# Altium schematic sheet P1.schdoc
size 297 x 209 mm; Symbol: Drawing-Symbol_A4; @Project Name: fmcw; @Page Count: 1; @Update Date: 2026-07-30; @Create Date: 2026-07-30; @Schematic Name: Schematic1; @Page No: 1; @Page Name: P1; Company: EasyEDA.com; Version: V1.0; Page Size: A4; Device: Drawing-Symbol_A4; @Create Time: 13:49:19; @Update Time: 13:49:19; Border: 1; Width: 1170; Height: 825; Region Start: 1; X Region Count: 6; Y Region Count: 4; Blade Width: 10; Title Block Position: 3; @Board Name: Board1
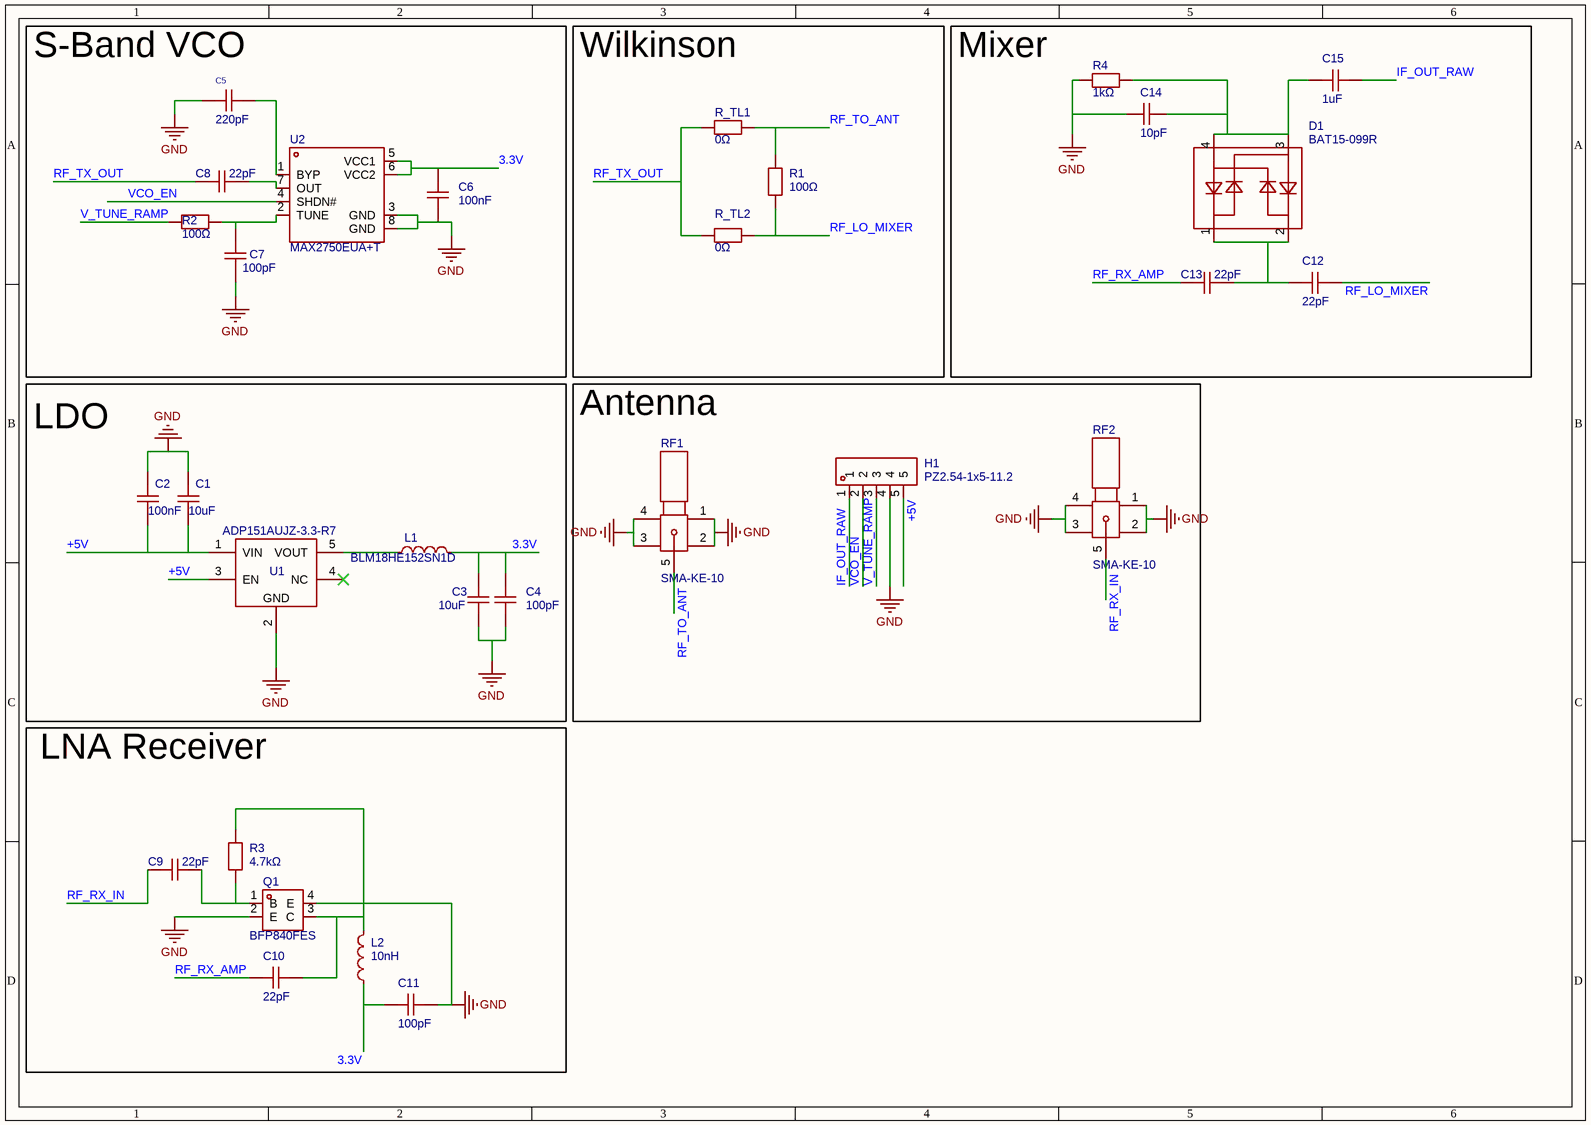
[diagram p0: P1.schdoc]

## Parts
C1  10uF  [C0805]
C2  100nF  [C0805]
C3  10uF  [C0805]
C4  100pF  [C0805]
C5  220pF  [C0603]
C6  100nF  [C0805]
C7  100pF  [C0805]
C8  22pF  [C0603]
C9  22pF  [C0603]
C10  22pF  [C0603]
C11  100pF  [C0805]
C12  22pF  [C0603]
C13  22pF  [C0603]
C14  10pF  [C0603]
C15  1uF  [C0402]
D1  BAT15-099R  [SOT-143-4_L2.9-W1.3-P1.92-LS2.3-BR]
H1  PZ2.54-1x5-11.2  [HDR-TH_5P-P2.54-V-M]
L1  BLM18HE152SN1D  [L0603]
L2  10nH  [L0402-RD]
Q1  BFP840FES  [TSFP-4-1_L1.4-W0.8-P1.00-LS1.2-TL-1]
R1  100Ω  [R0402]
R2  100Ω  [R0402]
R3  4.7kΩ  [R0402]
R4  1kΩ  [R0402]
R_TL1  0Ω  [R0402]
R_TL2  0Ω  [R0402]
RF1  SMA-KE-10  [SMA-TH_BWSMA-KE-Z001]
RF2  SMA-KE-10  [SMA-TH_BWSMA-KE-Z001]
U1  ADP151AUJZ-3.3-R7  [SOT-23-5_L3.0-W1.7-P0.95-LS2.8-BR]
U2  MAX2750EUA+T  [MSOP-8_L3.0-W3.0-P0.65-LS4.9-BL-1]

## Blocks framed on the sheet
S-Band VCO: C5-C8 R2 U2
Wilkinson: R1 R_TL1 R_TL2
Mixer: C12-C15 D1 R4
LDO: C1-C4 L1 U1
Antenna: H1 RF1 RF2
LNA Receiver: C9-C11 L2 Q1 R3

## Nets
GND: C1.1 C2.2 C3.1 C4.1 C5.1 C6.2 C7.2 C11.1 C14.2 H1.4 Q1.2(E) Q1.4(E) R4.1 RF1.1 RF1.2 RF1.3 RF1.4 RF2.1 RF2.2 RF2.3 RF2.4 U1.2(GND) U2.3(GND) U2.8(GND)
3.3V: C3.2 C4.2 C6.1 C11.2 L1.2 L2.1 U2.5(VCC1) U2.6(VCC2)
+5V: C1.2 C2.1 H1.5 U1.1(VIN) U1.3(EN)
IF_OUT_RAW: C15.1 H1.1
RF_LO_MIXER: C12.2 R1.1 R_TL2.2
RF_RX_AMP: C10.1 C13.2
RF_RX_IN: C9.2 RF2.5
RF_TO_ANT: R1.2 R_TL1.2 RF1.5
RF_TX_OUT: C8.2 R_TL1.1 R_TL2.1
V_TUNE_RAMP: H1.3 R2.1
VCO_EN: H1.2 U2.4(SHDN#)
NetC5_2: C5.2 U2.1(BYP)
NetC7_1: C7.1 R2.2 U2.2(TUNE)
NetC8_1: C8.1 U2.7(OUT)
NetC9_1: C9.1 Q1.1(B) R3.1
NetC10_2: C10.2 L2.2 Q1.3(C) R3.2
NetC12_1: C12.1 C13.1 D1.1 D1.2
NetC14_1: C14.1 C15.2 D1.3 D1.4 R4.2
NetL1_1: L1.1 U1.5(VOUT)

Not connected (* = marked no-connect by the designer): U1 4(NC)*

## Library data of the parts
C1 C3 = FCC0805X106K100FT: Capacitance:10uF Tolerance:±10% Tolerance:±10% Voltage Rating:10V Temperature Coefficient:X5R; Manufacturer: FOJAN(富捷); AddInBom: yes; ModelId: 8c88e81f49c6409b980720ec8953afb60819f05c4eef4c71ace90d822a990e87; ModelName: C0805_L2.0-W1.3-H1.3; ModelTransform: 78.74,51.181,0,0,0,0,0,0.0005,0; Tolerance: ±10%; Voltage Rating: 10V; Temperature Coefficient: X5R
C2 C6 = TCC0805X7R104K500DT: Capacitance:100nF Tolerance:±10% Tolerance:±10% Voltage Rating:50V Temperature Coefficient:X7R; Manufacturer: CCTC(三环); AddInBom: yes; ModelId: 8c88e81f49c6409b980720ec8953afb60819f05c4eef4c71ace90d822a990e87; ModelName: C0805_L2.0-W1.3-H1.3; ModelTransform: 78.74,51.181,0,0,0,0,0,0.0005,0; Tolerance: ±10%; Voltage Rating: 50V; Temperature Coefficient: X7R
C4 C7 C11 = 0805CG101J500NT: Capacitance:100pF Tolerance:±5% Tolerance:±5% Voltage Rating:50V Temperature Coefficient:C0G; Manufacturer: FH(风华); AddInBom: yes; ModelId: 8c88e81f49c6409b980720ec8953afb60819f05c4eef4c71ace90d822a990e87; ModelName: C0805_L2.0-W1.3-H1.3; ModelTransform: 78.74,51.181,0,0,0,0,0,0.0005,0; Tolerance: ±5%; Voltage Rating: 50V; Temperature Coefficient: C0G
C5 = GCM1885C2A221JA16D: Capacitance:220pF Tolerance:±5% Tolerance:±5% Voltage Rating:100V Temperature Coefficient:C0G; Manufacturer: muRata(村田); AddInBom: yes; ModelId: 624118aa3cc7497086c383c2d72e08520819f05c4eef4c71ace90d822a990e87; ModelName: C0603_L1.6-W0.8-H0.8; ModelTransform: 62.992,31.496,0,0,0,0,0,0,0; Tolerance: ±5%; Voltage Rating: 100V; Temperature Coefficient: C0G
C8-C10 C12 C13 = CL10C220JB8NNNC: Capacitance:22pF Tolerance:±5% Tolerance:±5% Voltage Rating:50V Temperature Coefficient:C0G; Manufacturer: SAMSUNG(三星); AddInBom: yes; ModelId: 624118aa3cc7497086c383c2d72e08520819f05c4eef4c71ace90d822a990e87; ModelName: C0603_L1.6-W0.8-H0.8; ModelTransform: 62.992,31.496,0,0,0,0,0,0,0; Tolerance: ±5%; Voltage Rating: 50V; Temperature Coefficient: C0G
C14 = CC0603JRNPO9BN100: Capacitance:10pF Tolerance:±5% Tolerance:±5% Voltage Rating:50V Temperature Coefficient:NP0; Manufacturer: YAGEO(国巨); AddInBom: yes; ModelId: 624118aa3cc7497086c383c2d72e08520819f05c4eef4c71ace90d822a990e87; ModelName: C0603_L1.6-W0.8-H0.8; ModelTransform: 62.992,31.496,0,0,0,0,0,0,0; Tolerance: ±5%; Voltage Rating: 50V; Temperature Coefficient: NP0
C15 = TCC0402X5R105M6R3AT: Capacitance:1uF Tolerance:±20% Tolerance:±20% Voltage Rating:6.3V Temperature Coefficient:X5R; Manufacturer: CCTC(三环); AddInBom: yes; ModelId: b7d13df3e9464d7a99d0651d1a5b4d570819f05c4eef4c71ace90d822a990e87; ModelName: C0402_L1.0-W0.5-H0.5; ModelTransform: 39.37,19.685,0,0,0,0,0,0,0; Tolerance: ±20%; Voltage Rating: 6.3V; Temperature Coefficient: X5R
D1 = BAT15-099R: Diode Configuration:2 Pair Common Cathode Voltage - Forward(Vf@If):410mV@10mA Voltage - DC Reverse(Vr):4V Current - Rectified:110mA Reverse Leakage Current (Ir):- Operating Junction Temperature Range:- Operating Junction Temperature Range:- Non-Repetitive; Manufacturer: Infineon(英飞凌); AddInBom: yes; ModelId: adc5bc672c5041b9a1ec0c11289de7190819f05c4eef4c71ace90d822a990e87; ModelName: SOT-143_L2.9-W1.3-H1.0-LS2.4-P1.92; ModelTransform: 114.173,94.488,0,90,0,0,0,0,0; Voltage - DC Reverse(Vr): 4V; Current - Rectified: 110mA
H1 = PZ2.54-1x5-11.2: Pin Structure:1x5P Pitch:2.54mm Circluar Pins/Square Pins:Pin Header Mounting Type:Through Hole Number of Rows:1 Number of Pins:5P Current Rating:2.5A Length of Mating Pin:5.7mm Insulation Height:2.54mm Length of End Connection Pin:3mm Contact Material:Br; Manufacturer: ZHOURI(洲日); AddInBom: yes; ModelId: 98c612b43cbb479a86eae3328ff22ecc0819f05c4eef4c71ace90d822a990e87; ModelName: HDR-TH_5P-P2.54-M-LI-1X5P; ModelTransform: 499.999,100,0,0,0,0,0,0,-118.11; Pin Structure: 1x5P; Pitch: 2.54mm; Current Rating: 2.5A
L1 = BLM18HE152SN1D: Impedance @ Frequency:1.5kΩ@100MHz Tolerance:±25% Tolerance:±25% DC Resistance(DCR):500mΩ Current Rating:500mA Number of Circuits:1 Operating Temperature:-55℃~+125℃ Operating Temperature:-55℃~+125℃; Manufacturer: muRata(村田); AddInBom: yes; ModelId: ece81e7160a84e0c9a4133ba5d41d18a0819f05c4eef4c71ace90d822a990e87; ModelName: L0603_L1.6-W0.8-H0.5_BEAD; ModelTransform: 62.992,31.496,0,180,0,0,0.094,0.629,0; Tolerance: ±25%; DC Resistance(DCR): 500mΩ; Current Rating: 500mA; Number of Circuits: 1
L2 = LQG15HS10NJ02D: Inductance:10nH Tolerance:±5% Tolerance:±5% Current Rating:500mA Current - Saturation (Isat):- DC Resistance(DCR):260mΩ Q @ Frequency:8@100MHz Frequency - Self Resonant:3.4GHz Ratings:-; Manufacturer: muRata(村田); AddInBom: yes; ModelId: af8519f297ad48beac83bdc898afdb0a0819f05c4eef4c71ace90d822a990e87; ModelTransform: 40.1574,20.4724,0,0,0,0,0,0,0; Tolerance: ±5%; Current Rating: 500mA; DC Resistance(DCR): 260mΩ; Frequency - Self Resonant: 3.4GHz
Q1 = BFP840FESDH6327XTSA1: type:NPN Current - Collector(Ic):35mA Collector - Emitter Voltage VCEO:2.25V Pd - Power Dissipation:75mW DC Current Gain:150@10mA,1.8V DC Current Gain:150@10mA,1.8V Transition frequency(fT):85GHz Current - Collector Cutoff:400nA Operating Temperature:-55℃; Manufacturer: Infineon(英飞凌); AddInBom: yes; ModelId: 34dd9e418b6d49dd8dbf5171623bd6570819f05c4eef4c71ace90d822a990e87; ModelTransform: 47.244,55.118,0,0,0,0,0,0,0; type: NPN; Current - Collector(Ic): 35mA; Collector - Emitter Voltage VCEO: 2.25V; Pd - Power Dissipation: 75mW; Transition frequency(fT): 85GHz; Current - Collector Cutoff: 400nA; Number: 1 NPN
R1 R2 = FRC0402J101 TS: Type:Thick Film Resistor Resistance:100Ω Tolerance:±5% Tolerance:±5% Power(Watts):62.5mW Voltage-Supply(Max):50V Temperature Coefficient:±100ppm/℃ Temperature Coefficient:±100ppm/℃ Operating Temperature:-55℃~+155℃ Operating Temperature:-55℃~+155℃; Manufacturer: FOJAN(富捷); AddInBom: yes; ModelId: efdecb7dae4442949d28eecaf748420f0819f05c4eef4c71ace90d822a990e87; ModelName: R0402_L1.0-W0.5-H0.4; ModelTransform: 39.37,19.685,0,0,0,0,0,0,0; Tolerance: ±5%; Power(Watts): 62.5mW; Voltage-Supply(Max): 50V
R3 = FRC0402J472 TS: Type:Thick Film Resistor Resistance:4.7kΩ Tolerance:±5% Tolerance:±5% Power(Watts):62.5mW Voltage-Supply(Max):50V Temperature Coefficient:±100ppm/℃ Temperature Coefficient:±100ppm/℃ Operating Temperature:-55℃~+155℃ Operating Temperature:-55℃~+155℃; Manufacturer: FOJAN(富捷); AddInBom: yes; ModelId: efdecb7dae4442949d28eecaf748420f0819f05c4eef4c71ace90d822a990e87; ModelName: R0402_L1.0-W0.5-H0.4; ModelTransform: 39.37,19.685,0,0,0,0,0,0,0; Tolerance: ±5%; Power(Watts): 62.5mW; Voltage-Supply(Max): 50V
R4 = FRC0402J102 TS: Type:Thick Film Resistor Resistance:1kΩ Tolerance:±5% Tolerance:±5% Power(Watts):62.5mW Voltage-Supply(Max):50V Temperature Coefficient:±100ppm/℃ Temperature Coefficient:±100ppm/℃ Operating Temperature:-55℃~+155℃ Operating Temperature:-55℃~+155℃; Manufacturer: FOJAN(富捷); AddInBom: yes; ModelId: efdecb7dae4442949d28eecaf748420f0819f05c4eef4c71ace90d822a990e87; ModelName: R0402_L1.0-W0.5-H0.4; ModelTransform: 39.37,19.685,0,0,0,0,0,0,0; Tolerance: ±5%; Power(Watts): 62.5mW; Voltage-Supply(Max): 50V
R_TL1 R_TL2 = FRC0402P000 TS: Type:Thick Film Resistor Resistance:0Ω Tolerance:±5% Tolerance:±5% Power(Watts):62.5mW Voltage-Supply(Max):50V Operating Temperature:-55℃~+155℃ Operating Temperature:-55℃~+155℃; Manufacturer: FOJAN(富捷); AddInBom: yes; ModelId: efdecb7dae4442949d28eecaf748420f0819f05c4eef4c71ace90d822a990e87; ModelName: R0402_L1.0-W0.5-H0.4; ModelTransform: 39.37,19.685,0,0,0,0,0,0,0; Tolerance: ±5%; Power(Watts): 62.5mW; Voltage-Supply(Max): 50V
RF1 RF2 = SMA-KE-10: Connector Type:Board Side Interface:Inner Bore Number of Ports:1 Interface Length/Height:8mm RF Series:SMA Impedance:50Ω Style:Positive Pin Operating Temperature Range:-40℃~+125℃ Operating Temperature Range:-40℃~+125℃; Manufacturer: Ziisor(致哲); AddInBom: yes; ModelId: f6f48ffe9da340b09a5b7cf26dc9292d0819f05c4eef4c71ace90d822a990e87; ModelName: SMA-TH_5P-L6.5-W6.5-H9.8_BWSMA-KE-Z001; ModelTransform: 255.905,255.905,0,0,0,0,0,0,-137.795; Number of Ports: 1; Interface Length/Height: 8mm; RF Series: SMA; Impedance: 50Ω
U1 = ADP151AUJZ-3.3-R7: Output Configuration:Positive Voltage - Supply:5.5V Output Voltage:3.3V Output Voltage:3.3V Output Current:200mA Power Supply Rejection Ratio (PSRR):70dB@(10kHz)；55dB@(100kHz) Voltage Dropout:230mV@(200mA) standby current:- Noise:9uVrms Features:Enable co; Manufacturer: ADI(亚德诺); AddInBom: yes; ModelId: 3168b22659ce4998ae232d44bb704e0a0819f05c4eef4c71ace90d822a990e87; ModelName: SOT-23-5_L2.9-W1.6-H1.1-LS2.8-P0.95; ModelTransform: 114.173,109.636,0,180,0,0,0,0,0; Voltage - Supply: 5.5V; Output Voltage: 3.3V; Noise: 9uVrms; Output Type: Fixed; Number of Outputs: 1
U2 = MAX2750EUA+T: Applications:ISM Function:VCO Frequency Range:2.4GHz~2.5GHz Frequency Range:2.4GHz~2.5GHz; Manufacturer: ADI(亚德诺)/MAXIM(美信); AddInBom: yes; ModelId: 897b7883b5224015b18eb876d042238f0819f05c4eef4c71ace90d822a990e87; ModelTransform: 118.11,192.913,0,0,0,0,0,0,0; Function: VCO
